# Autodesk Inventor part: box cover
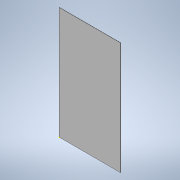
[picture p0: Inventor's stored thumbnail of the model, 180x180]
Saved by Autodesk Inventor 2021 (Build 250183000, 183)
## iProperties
Created: 2021-07
Part Number: box cover
Material: Generic
Document SubType Name: Modeling
Designer: CHIRAG
Density: 1 g/cm^3
Appearance: Default
Author: CHIRAG
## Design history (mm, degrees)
sketch "Sketch1"
  geometry: 1 further point
sketch "Sketch2"
  geometry: L1 (0, 0)-(300, 0); L2 (300, 0)-(300, 550); L3 (300, 550)-(0, 550); L4 (0, 550)-(0, 0)
  constraints: 8 end point, 2 parallel, 1 horizontal, 1 perpendicular
  dimensions: "d0" = 300 distance of L3.end L2.end; "d1" = 550 distance of L2.end L1.end
extrude "Extrusion1" new body sketch "Sketch2" distance "d2" = 1; taper "d3" = 0 deg
sketch "Sketch3"
  geometry: 1 further point
body "Solid1"
